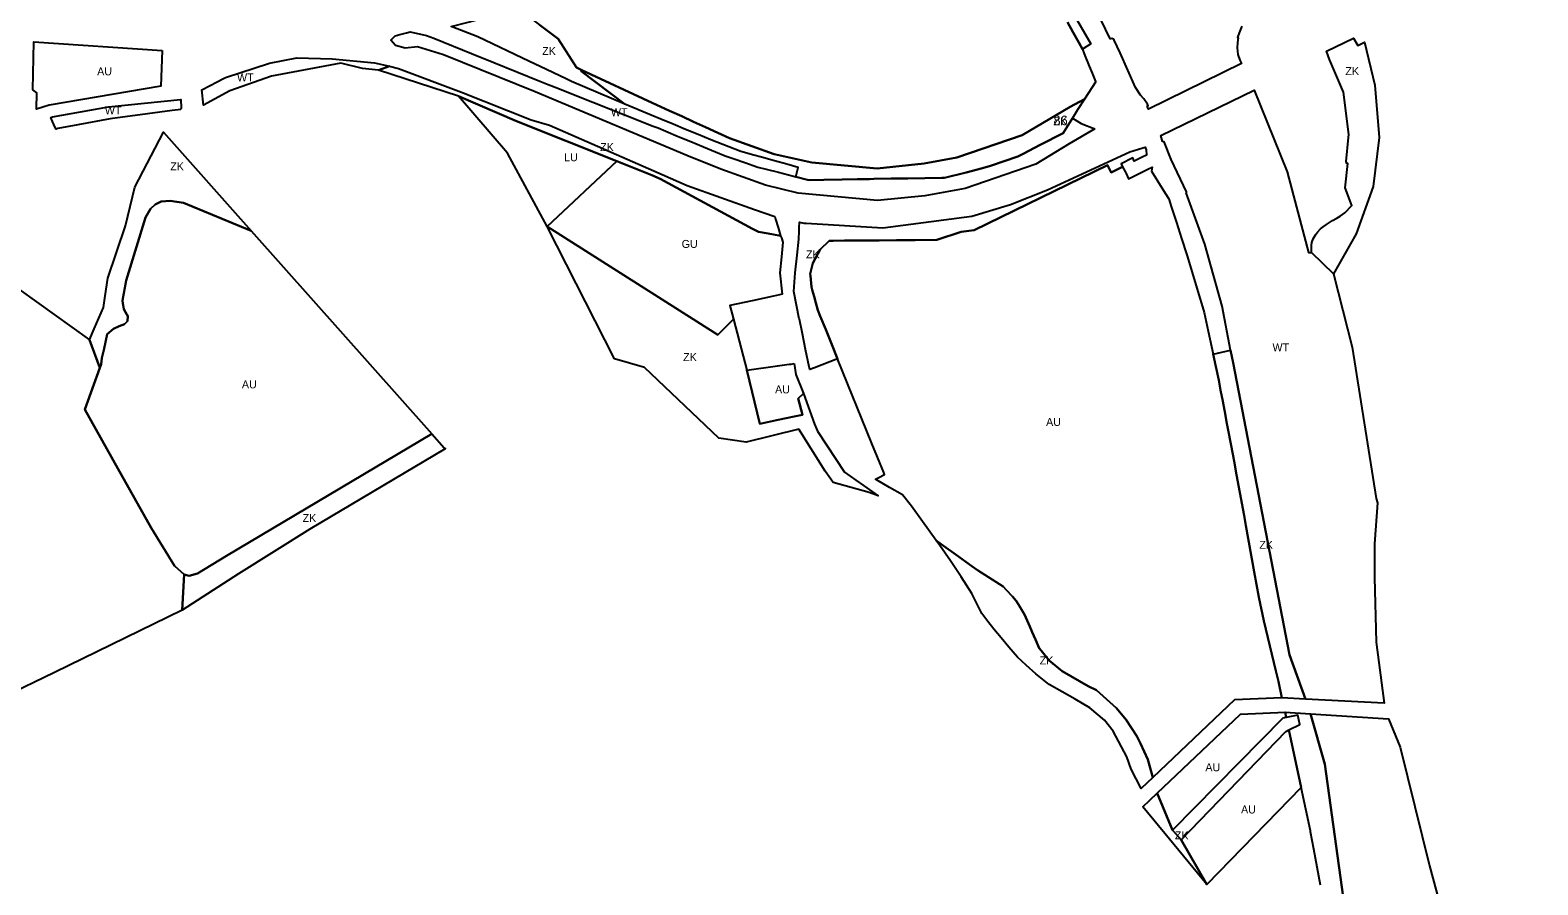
# Model space of a CAD drawing. Extents: x -535894 to -532834, y -1165802 to -1163647.
# Drawn here: x -533821 to -532878, y -1165346 to -1164811 of the extents above; entities that cross this region are included whole.
import ezdxf

# ---------------------------------------------------------------- set-up
doc = ezdxf.new("R2010")
doc.units = 0
for name, color, linetype in [('Vrstva 16', 7, 'Continuous'), ('Vrstva 17', 7, 'Continuous'), ('Vrstva 19', 7, 'Continuous'), ('Vrstva 20', 7, 'Continuous'), ('Vrstva 22', 7, 'Continuous'), ('Vrstva 28', 7, 'Continuous'), ('Vrstva 37', 7, 'Continuous'), ('Vrstva 4', 7, 'Continuous'), ('Vrstva 61', 7, 'Continuous')]:
    doc.layers.add(name, color=color, linetype=linetype)

msp = doc.modelspace()

# ---------------------------------------------------------------- linework, layer by layer
at = {"layer": 'Vrstva 16'}
for points in [[(-533449.329, -1164857.017), (-533482.547, -1164842.741), (-533485.98, -1164841.17), (-533502.187, -1164833.429), (-533508.929, -1164830.209), (-533541.19, -1164814.8), (-533557.97, -1164808.32), (-533538.206, -1164803.326), (-533528.49, -1164803.93), (-533518.46, -1164795.33), (-533502.549, -1164807.296), (-533491.019, -1164815.967), (-533479.52, -1164834.02), (-533476.1, -1164835.72), (-533476.589, -1164836.253)], [(-533019.65, -1164949.83), (-533019.75, -1164945.44), (-533019.74, -1164945.35), (-533019.5, -1164943.61), (-533018.74, -1164941.21), (-533017.27, -1164938.72), (-533016.06, -1164937.15), (-533014.17, -1164935.04), (-533012.47, -1164933.65), (-533010.36, -1164932.29), (-533009.67, -1164931.84), (-533006.56, -1164929.76), (-533003.92, -1164928.32), (-533001.85, -1164927.06), (-532998.95, -1164924.85), (-532994.46, -1164920.43), (-532998.63, -1164909.37), (-532997.02, -1164894.02), (-532997.55, -1164893.98), (-532997.96, -1164892.84), (-532996.596, -1164877.755), (-532996.43, -1164875.92), (-532999.79, -1164849.41), (-533008.53, -1164829.07), (-533010.27, -1164823.69), (-532993.57, -1164815.7), (-532990.84, -1164820.26), (-532986.56, -1164818.1), (-532980.17, -1164845.09), (-532977.31, -1164877.84), (-532981.22, -1164908.52), (-532991.79, -1164937.99), (-533005.91, -1164963.1)], [(-533351.86, -1164939.38), (-533356.31, -1164938.57), (-533359.67, -1164937.97), (-533365.69, -1164936.87), (-533367.68, -1164935.8), (-533369.34, -1164934.9), (-533427.21, -1164903.65), (-533432.31, -1164901.38), (-533454.32, -1164892.58), (-533516.99, -1164867.54), (-533553.28, -1164851.89), (-533603.37, -1164835.56), (-533596.46, -1164833.25), (-533590.786, -1164834.559), (-533551.367, -1164849.4), (-533507.739, -1164866.745), (-533496.424, -1164870.179), (-533431.14, -1164898.61), (-533425.87, -1164900.96), (-533410.244, -1164907.892), (-533368.121, -1164922.828), (-533355.407, -1164927.219), (-533354.932, -1164928.848), (-533353.414, -1164934.051)], [(-533784.18, -1165004.34), (-533781.22, -1164997.48), (-533775.32, -1164984.22), (-533774.28, -1164976.84), (-533772.59, -1164965.85), (-533761.58, -1164933.18), (-533755.71, -1164908.94), (-533737.9, -1164874.36), (-533682.961, -1164936.173), (-533725.33, -1164918.79), (-533733.55, -1164917.49), (-533739.33, -1164917.78), (-533742.93, -1164919.66), (-533745.96, -1164922.55), (-533749, -1164927.89), (-533761.12, -1164967.31), (-533763.43, -1164979.87), (-533763.28, -1164981.75), (-533762.56, -1164985.07), (-533762.13, -1164986.08), (-533760.11, -1164989.55), (-533760.4, -1164992.72), (-533762.27, -1164994.6), (-533765.59, -1164995.9), (-533769.06, -1164997.49), (-533772.95, -1165000.81), (-533774.948, -1165009.851), (-533776.27, -1165015.83), (-533776.85, -1165019.72), (-533777.72, -1165022.03)], [(-533127.88, -1164885.08), (-533123.831, -1164883.862), (-533123.175, -1164885.463), (-533122.912, -1164888.766), (-533125.56, -1164890.06), (-533130.56, -1164892.51), (-533131.5, -1164890.61), (-533138.79, -1164894.19), (-533137.86, -1164896.07), (-533145.13, -1164899.63), (-533147.32, -1164895.13), (-533230.7, -1164935.9), (-533238.8, -1164936.84), (-533254.19, -1164941.95), (-533267.6, -1164942.04), (-533279.34, -1164942.12), (-533290.22, -1164942.19), (-533299.86, -1164942.25), (-533309.61, -1164942.31), (-533311.84, -1164942.33), (-533318.89, -1164942.38), (-533321.4, -1164942.4), (-533327.086, -1164947.81), (-533331.63, -1164956.4), (-533333.27, -1164963.05), (-533333.139, -1164964.439), (-533332.5, -1164971.24), (-533331.983, -1164973.183), (-533330.86, -1164977.41), (-533329.794, -1164981.317), (-533328.55, -1164985.88), (-533327.03, -1164989.6), (-533323.61, -1164998.03), (-533319.84, -1165007.34), (-533316.16, -1165016.4), (-533330.632, -1165021.862), (-533333.62, -1165022.99), (-533333.91, -1165021.36), (-533336.164, -1165010.56), (-533338.183, -1165000.693), (-533340.069, -1164991.475), (-533340.094, -1164991.354), (-533341.865, -1164982.699), (-533343.59, -1164974.269), (-533342.636, -1164962.604), (-533341.509, -1164951.373), (-533340.51, -1164941.413), (-533340.301, -1164936.333), (-533340.209, -1164934.096), (-533340.076, -1164930.725), (-533337.2, -1164931.49), (-533335.892, -1164931.357), (-533287.795, -1164934.442), (-533232.144, -1164926.953), (-533207.984, -1164919.73), (-533184.943, -1164910.649), (-533133.323, -1164886.788)], [(-533340.42, -1165060.46), (-533373.45, -1165068.48), (-533390.5, -1165066.09), (-533436.96, -1165021.83), (-533455.65, -1165016.42), (-533497.72, -1164933.47), (-533391.12, -1165001.26), (-533381.33, -1164991.55), (-533372.98, -1165023.48), (-533364.81, -1165056.97), (-533353.28, -1165054.53), (-533343.29, -1165052.42), (-533338.04, -1165051.31), (-533340.73, -1165041.06), (-533337.57, -1165038.08), (-533330.525, -1165057.282), (-533328.63, -1165061.62), (-533311.86, -1165087.17), (-533304.665, -1165092.211), (-533299.889, -1165095.558), (-533290.68, -1165102.01), (-533296.36, -1165099.92), (-533318.84, -1165093.8), (-533324, -1165086.69)], [(-533038.193, -1165228.594), (-533040.38, -1165218.35), (-533041.97, -1165211.69), (-533049.49, -1165180.28), (-533052.58, -1165165.52), (-533055.7, -1165149.58), (-533060.76, -1165120.61), (-533061.85, -1165114.35), (-533064.51, -1165100.09), (-533066.59, -1165088.96), (-533068.21, -1165080.3), (-533070.04, -1165070.55), (-533072, -1165060.03), (-533072.81, -1165055.68), (-533073.57, -1165051.71), (-533075.28, -1165042.82), (-533076.61, -1165035.87), (-533077.78, -1165029.77), (-533079.658, -1165021.038), (-533081.32, -1165013.31), (-533070.375, -1165010.82), (-533068.828, -1165018.82), (-533033.46, -1165201.68), (-533023.406, -1165229.36)], [(-533724.81, -1165151.41), (-533721.78, -1165152.17), (-533716.48, -1165150.65), (-533698.37, -1165139.6), (-533570, -1165063.27), (-533562.167, -1165071.953), (-533561.35, -1165072.56), (-533561.52, -1165072.67), (-533646.35, -1165122.98), (-533690.81, -1165150.82), (-533726.09, -1165173.68)], [(-533119.066, -1165278.401), (-533126.238, -1165285.22), (-533132.616, -1165273.134), (-533135.154, -1165265.393), (-533143.803, -1165249.375), (-533149.315, -1165242.562), (-533158.312, -1165234.728), (-533167.647, -1165229.437), (-533183.904, -1165220.221), (-533192.12, -1165213.6), (-533198.238, -1165208.072), (-533203.683, -1165203.151), (-533209.065, -1165196.853), (-533213.92, -1165190.884), (-533218.343, -1165185.445), (-533222.253, -1165180.637), (-533225.922, -1165175.806), (-533232.175, -1165163.211), (-533238.958, -1165152.798), (-533245.578, -1165142.723), (-533252.308, -1165133.249), (-533254.581, -1165130.049), (-533251.367, -1165132.338), (-533241.903, -1165139.078), (-533232.151, -1165146.023), (-533228.63, -1165148.53), (-533221.834, -1165152.934), (-533212.69, -1165158.86), (-533210.794, -1165160.894), (-533206.861, -1165165.113), (-533204.43, -1165167.72), (-533202.96, -1165170.109), (-533199.282, -1165176.366), (-533196.01, -1165183.82), (-533194.4, -1165187.49), (-533192.444, -1165191.932), (-533189.98, -1165197.53), (-533188.886, -1165198.883), (-533183.78, -1165205.2), (-533183.758, -1165205.218), (-533175.591, -1165211.807), (-533159.489, -1165221.131), (-533154.28, -1165223.8), (-533141.737, -1165235.035), (-533135.7, -1165242.39), (-533128.91, -1165252.43), (-533126.777, -1165257.07), (-533122.13, -1165267.18)], [(-533116.373, -1165288.26), (-533106.758, -1165311.449), (-533104.858, -1165313.507), (-533101.358, -1165317.299), (-533085.21, -1165345.43), (-533108.53, -1165316.98), (-533125.197, -1165296.649), (-533120.847, -1165292.513)]]:
    msp.add_lwpolyline(points, close=True, dxfattribs=at)
msp.add_lwpolyline([(-533014.2, -1165345.74), (-533018.3, -1165323.32), (-533020.29, -1165312.45), (-533020.4, -1165311.8), (-533026.24, -1165284.54), (-533033.915, -1165248.628), (-533026.975, -1165245.213), (-533028.21, -1165239.43), (-533035.573, -1165240.864), (-533036.286, -1165237.524), (-533020.388, -1165238.55), (-533011.43, -1165270.01), (-532970.84, -1165564.38)], dxfattribs=at)
at = {"layer": 'Vrstva 17'}
msp.add_lwpolyline([(-533449.329, -1164857.017), (-533476.589, -1164836.253), (-533476.1, -1164835.72), (-533432.125, -1164855.996), (-533421.201, -1164861.033), (-533413.65, -1164864.514), (-533406.222, -1164867.94), (-533398.688, -1164871.413), (-533390.995, -1164874.961), (-533383.775, -1164878.254), (-533355.854, -1164888.263), (-533332.237, -1164893.383), (-533291.404, -1164897.211), (-533261.946, -1164894.083), (-533241.514, -1164890.305), (-533200.695, -1164876.243), (-533170.75, -1164858.64), (-533161.703, -1164853.84), (-533166.05, -1164860.58), (-533169.319, -1164865.777), (-533175.17, -1164875.08), (-533189.49, -1164882.49), (-533200, -1164887.93), (-533203.49, -1164889.74), (-533220.52, -1164895.43), (-533225.42, -1164897.07), (-533235.8, -1164899.62), (-533249.36, -1164902.96), (-533251.03, -1164902.99), (-533261.52, -1164903.19), (-533272.33, -1164903.38), (-533282.57, -1164903.56), (-533293.4, -1164903.76), (-533296.3, -1164903.82), (-533303.94, -1164903.95), (-533313.39, -1164904.12), (-533324.7, -1164904.32), (-533333.91, -1164904.48), (-533334.89, -1164904.23), (-533342.327, -1164902.343), (-533341.727, -1164900.001), (-533340.838, -1164896.53), (-533347.953, -1164894.562), (-533355.604, -1164892.445), (-533363.81, -1164890.174), (-533368.48, -1164888.881), (-533376.769, -1164886.588), (-533387.877, -1164882.185), (-533395.416, -1164879.165), (-533403.421, -1164875.924), (-533411.249, -1164872.7), (-533418.937, -1164869.534), (-533426.826, -1164866.284), (-533432.806, -1164863.822)], close=True, dxfattribs=at)
at = {"layer": 'Vrstva 19'}
msp.add_lwpolyline([(-533828.25, -1164972.65), (-533784.18, -1165004.34), (-533777.72, -1165022.03), (-533786.95, -1165048.06), (-533766.306, -1165084.954), (-533745.52, -1165122.1), (-533730.88, -1165145.85), (-533724.81, -1165151.41), (-533726.09, -1165173.68), (-533806.07, -1165212.59), (-533837.937, -1165228.09)], dxfattribs=at)
at = {"layer": 'Vrstva 20'}
msp.add_lwpolyline([(-533183.34, -1164774.65), (-533157.83, -1164819.27), (-533163.04, -1164822.52), (-533165.34, -1164818.38), (-533168.77, -1164812.17), (-533172.45, -1164805.52)], dxfattribs=at)
at = {"layer": 'Vrstva 22'}
msp.add_lwpolyline([(-533172.45, -1164805.52), (-533168.77, -1164812.17), (-533165.34, -1164818.38), (-533163.04, -1164822.52), (-533161.85, -1164825.47), (-533158.74, -1164833.17), (-533156.99, -1164837.52), (-533154.89, -1164842.74), (-533154.75, -1164843.06), (-533161.703, -1164853.84), (-533170.75, -1164858.64), (-533200.695, -1164876.243), (-533241.514, -1164890.305), (-533261.946, -1164894.083), (-533291.404, -1164897.211), (-533332.237, -1164893.383), (-533355.854, -1164888.263), (-533383.775, -1164878.254), (-533390.995, -1164874.961), (-533398.688, -1164871.413), (-533406.222, -1164867.94), (-533413.65, -1164864.514), (-533421.201, -1164861.033), (-533432.125, -1164855.996), (-533476.1, -1164835.72), (-533479.52, -1164834.02), (-533491.019, -1164815.967), (-533502.549, -1164807.296)], dxfattribs=at)
for points in [[(-533738.69, -1164823.39), (-533739.473, -1164845.641), (-533809.264, -1164857.538), (-533817.166, -1164859.962), (-533817.069, -1164849.817), (-533819.587, -1164847.865), (-533818.847, -1164817.831)], [(-533119.066, -1165278.401), (-533122.13, -1165267.18), (-533126.777, -1165257.07), (-533128.91, -1165252.43), (-533135.7, -1165242.39), (-533141.737, -1165235.035), (-533154.28, -1165223.8), (-533159.489, -1165221.131), (-533175.591, -1165211.807), (-533183.758, -1165205.218), (-533183.78, -1165205.2), (-533188.886, -1165198.883), (-533189.98, -1165197.53), (-533192.444, -1165191.932), (-533194.4, -1165187.49), (-533196.01, -1165183.82), (-533199.282, -1165176.366), (-533202.96, -1165170.109), (-533204.43, -1165167.72), (-533206.861, -1165165.113), (-533210.794, -1165160.894), (-533212.69, -1165158.86), (-533221.834, -1165152.934), (-533228.63, -1165148.53), (-533232.151, -1165146.023), (-533241.903, -1165139.078), (-533251.367, -1165132.338), (-533254.581, -1165130.049), (-533258.331, -1165124.77), (-533264.059, -1165116.707), (-533269.885, -1165108.505), (-533275.616, -1165101.51), (-533283.754, -1165096.808), (-533291.871, -1165092.117), (-533292.517, -1165091.744), (-533290.36, -1165090.63), (-533286.76, -1165088.76), (-533287.25, -1165087.56), (-533291.2, -1165077.84), (-533294.68, -1165069.27), (-533316.16, -1165016.4), (-533319.84, -1165007.34), (-533323.61, -1164998.03), (-533327.03, -1164989.6), (-533328.55, -1164985.88), (-533329.794, -1164981.317), (-533330.86, -1164977.41), (-533331.983, -1164973.183), (-533332.5, -1164971.24), (-533333.139, -1164964.439), (-533333.27, -1164963.05), (-533331.63, -1164956.4), (-533327.086, -1164947.81), (-533321.4, -1164942.4), (-533318.89, -1164942.38), (-533311.84, -1164942.33), (-533309.61, -1164942.31), (-533299.86, -1164942.25), (-533290.22, -1164942.19), (-533279.34, -1164942.12), (-533267.6, -1164942.04), (-533254.19, -1164941.95), (-533238.8, -1164936.84), (-533230.7, -1164935.9), (-533147.32, -1164895.13), (-533145.13, -1164899.63), (-533137.86, -1164896.07), (-533136.13, -1164899.58), (-533135.74, -1164900.39), (-533134.16, -1164903.63), (-533132.1, -1164902.62), (-533122.04, -1164897.68), (-533119.37, -1164896.37), (-533119.82, -1164898.82), (-533117.14, -1164903.15), (-533116.11, -1164904.82), (-533111.26, -1164912.65), (-533109.04, -1164916.24), (-533107.52, -1164920.92), (-533104.27, -1164930.9), (-533100.95, -1164941.1), (-533097.74, -1164951.15), (-533094.38, -1164962.37), (-533090.86, -1164974.13), (-533087.36, -1164985.79), (-533086.92, -1164987.26), (-533084.4, -1164998.97), (-533081.32, -1165013.31), (-533079.658, -1165021.038), (-533077.78, -1165029.77), (-533076.61, -1165035.87), (-533075.28, -1165042.82), (-533073.57, -1165051.71), (-533072.81, -1165055.68), (-533072, -1165060.03), (-533070.04, -1165070.55), (-533068.21, -1165080.3), (-533066.59, -1165088.96), (-533064.51, -1165100.09), (-533061.85, -1165114.35), (-533060.76, -1165120.61), (-533055.7, -1165149.58), (-533052.58, -1165165.52), (-533049.49, -1165180.28), (-533041.97, -1165211.69), (-533040.38, -1165218.35), (-533038.193, -1165228.594), (-533067.971, -1165229.821)], [(-533777.72, -1165022.03), (-533776.85, -1165019.72), (-533776.27, -1165015.83), (-533774.948, -1165009.851), (-533772.95, -1165000.81), (-533769.06, -1164997.49), (-533765.59, -1164995.9), (-533762.27, -1164994.6), (-533760.4, -1164992.72), (-533760.11, -1164989.55), (-533762.13, -1164986.08), (-533762.56, -1164985.07), (-533763.28, -1164981.75), (-533763.43, -1164979.87), (-533761.12, -1164967.31), (-533749, -1164927.89), (-533745.96, -1164922.55), (-533742.93, -1164919.66), (-533739.33, -1164917.78), (-533733.55, -1164917.49), (-533725.33, -1164918.79), (-533682.961, -1164936.173), (-533570, -1165063.27), (-533698.37, -1165139.6), (-533716.48, -1165150.65), (-533721.78, -1165152.17), (-533724.81, -1165151.41), (-533730.88, -1165145.85), (-533745.52, -1165122.1), (-533766.306, -1165084.954), (-533786.95, -1165048.06)], [(-533343.416, -1165019.324), (-533342.183, -1165026.234), (-533337.57, -1165038.08), (-533340.73, -1165041.06), (-533338.04, -1165051.31), (-533343.29, -1165052.42), (-533353.28, -1165054.53), (-533364.81, -1165056.97), (-533372.98, -1165023.48), (-533353.73, -1165020.77), (-533346.35, -1165019.74), (-533345.15, -1165019.57)], [(-533037.66, -1165241.27), (-533106.758, -1165311.449), (-533116.373, -1165288.26), (-533064.221, -1165238.674), (-533036.286, -1165237.524), (-533035.573, -1165240.864)], [(-533033.915, -1165248.628), (-533026.24, -1165284.54), (-533085.21, -1165345.43), (-533101.358, -1165317.299), (-533035.85, -1165249.58)]]:
    msp.add_lwpolyline(points, close=True, dxfattribs=at)
at = {"layer": 'Vrstva 28'}
msp.add_lwpolyline([(-533516.99, -1164867.54), (-533454.32, -1164892.58), (-533497.72, -1164933.47), (-533522.7, -1164887.69), (-533553.28, -1164851.89)], close=True, dxfattribs=at)
at = {"layer": 'Vrstva 37'}
msp.add_lwpolyline([(-533367.68, -1164935.8), (-533365.69, -1164936.87), (-533359.67, -1164937.97), (-533356.31, -1164938.57), (-533351.86, -1164939.38), (-533351.34, -1164940.58), (-533350.481, -1164943.362), (-533351.343, -1164952.464), (-533352.303, -1164962.6), (-533350.73, -1164975.81), (-533352.5, -1164976.21), (-533356.25, -1164977.03), (-533369.51, -1164979.95), (-533383.55, -1164983.05), (-533381.33, -1164991.55), (-533391.12, -1165001.26), (-533497.72, -1164933.47), (-533454.32, -1164892.58), (-533432.31, -1164901.38), (-533427.21, -1164903.65), (-533369.34, -1164934.9)], close=True, dxfattribs=at)
at = {"layer": 'Vrstva 4'}
msp.add_lwpolyline([(-533063.41, -1164808.03), (-533064.98, -1164812.34), (-533066.05, -1164815.28), (-533065.52, -1164815.47), (-533066.12, -1164818.42), (-533066.32, -1164821.75), (-533065.88, -1164825.93), (-533064.62, -1164829.31), (-533063.56, -1164831.41), (-533121.79, -1164860.11), (-533122.6, -1164858.35), (-533121.94, -1164858.07), (-533122.39, -1164856.98), (-533124.52, -1164853.64), (-533126.75, -1164851.21), (-533129.85, -1164846.49), (-533139.39, -1164824.708), (-533143.209, -1164816.81), (-533143.6, -1164816.322), (-533144.251, -1164815.953), (-533144.641, -1164815.909), (-533145.227, -1164815.953), (-533145.683, -1164816.04), (-533171.85, -1164761.354)], dxfattribs=at)
for points in [[(-533155.355, -1164872.361), (-533171.4, -1164881.68), (-533192.2, -1164894.47), (-533236.41, -1164909.7), (-533261.61, -1164914.36), (-533291.28, -1164917.31), (-533340.78, -1164912.67), (-533361.33, -1164907.54), (-533389.23, -1164897.67), (-533410.4, -1164889.02), (-533505.42, -1164849.16), (-533562.74, -1164826), (-533578.89, -1164821.11), (-533586.7, -1164821.82), (-533592.59, -1164820.3), (-533595.59, -1164816.83), (-533592.91, -1164814.08), (-533589.91, -1164813.28), (-533585.817, -1164812.22), (-533583.58, -1164811.64), (-533573.32, -1164813.85), (-533568.75, -1164815.7), (-533545.15, -1164825.22), (-533531.09, -1164830.9), (-533502.39, -1164842.48), (-533497.24, -1164844.53), (-533491.23, -1164846.91), (-533487.68, -1164848.33), (-533431.47, -1164870.62), (-533428.43, -1164871.84), (-533423.51, -1164873.88), (-533415.86, -1164877.07), (-533408.04, -1164880.32), (-533400.11, -1164883.63), (-533392.63, -1164886.74), (-533386.52, -1164889.28), (-533381.38, -1164891.04), (-533373.49, -1164893.74), (-533369.05, -1164895.26), (-533365.96, -1164896.32), (-533360.93, -1164897.6), (-533353.15, -1164899.58), (-533343.76, -1164901.98), (-533342.327, -1164902.343), (-533334.89, -1164904.23), (-533333.91, -1164904.48), (-533324.7, -1164904.32), (-533313.39, -1164904.12), (-533303.94, -1164903.95), (-533296.3, -1164903.82), (-533293.4, -1164903.76), (-533282.57, -1164903.56), (-533272.33, -1164903.38), (-533261.52, -1164903.19), (-533251.03, -1164902.99), (-533249.36, -1164902.96), (-533235.8, -1164899.62), (-533225.42, -1164897.07), (-533220.52, -1164895.43), (-533203.49, -1164889.74), (-533200, -1164887.93), (-533189.49, -1164882.49), (-533175.17, -1164875.08), (-533169.319, -1164865.777), (-533163.824, -1164869.081)], [(-533654.486, -1164827.886), (-533632.378, -1164828.501), (-533605.839, -1164831.108), (-533596.46, -1164833.25), (-533603.37, -1164835.56), (-533613.25, -1164834.55), (-533626.96, -1164831.3), (-533670.19, -1164839.35), (-533696.31, -1164848.54), (-533712.834, -1164857.586), (-533713.818, -1164847.949), (-533704.29, -1164842.98), (-533700.79, -1164841.16), (-533699.02, -1164840.23), (-533671.59, -1164831.22)], [(-533023.406, -1165229.36), (-533033.46, -1165201.68), (-533068.828, -1165018.82), (-533070.375, -1165010.82), (-533075.69, -1164983.34), (-533086.39, -1164944.59), (-533098.11, -1164912.42), (-533097.896, -1164912.121), (-533097.918, -1164911.73), (-533107.544, -1164891.527), (-533111.8, -1164880.45), (-533113, -1164880.39), (-533113.94, -1164876.55), (-533055.68, -1164848.17), (-533035.02, -1164899.39), (-533024.33, -1164939.46), (-533021.57, -1164949.83), (-533019.65, -1164949.83), (-533005.91, -1164963.1), (-532994.2, -1165009.04), (-532979.21, -1165103.79), (-532978.36, -1165106.4), (-532980.41, -1165132.1), (-532980.24, -1165153.13), (-532979.22, -1165193.65), (-532974.335, -1165231.899)], [(-533726.94, -1164860.18), (-533728.63, -1164860.41), (-533732.38, -1164860.92), (-533747.79, -1164863), (-533771.09, -1164866.14), (-533791.44, -1164869.9), (-533803.9, -1164872.2), (-533804.975, -1164872.651), (-533805.67, -1164871.11), (-533807.83, -1164866.32), (-533808.265, -1164865.356), (-533807.19, -1164864.79), (-533772.11, -1164858.69), (-533727.16, -1164854.1), (-533726.9, -1164854), (-533726.73, -1164859.25)], [(-532880.194, -1165591.758), (-532908.13, -1165601.07), (-532938.91, -1165611.34), (-532953.65, -1165616.26), (-532955.6, -1165612.74), (-532958.061, -1165604.931), (-532970.84, -1165564.38), (-533011.43, -1165270.01), (-533020.388, -1165238.55), (-532971.48, -1165241.706), (-532964.21, -1165259.48), (-532945.97, -1165333.71), (-532926.98, -1165404.07), (-532896.21, -1165523.88), (-532889.53, -1165558.14), (-532878.16, -1165591.08)]]:
    msp.add_lwpolyline(points, close=True, dxfattribs=at)

# ---------------------------------------------------------------- texts
at = {"layer": 'Vrstva 16'}
for rotation, p in [(360, (-533500.9479, -1164826.1735)), (359.9999999, (-532998.53, -1164838.7122)), (360, (-533464.6861, -1164886.315)), (0.0000001, (-533733.5705, -1164898.3611)), (360, (-533335.8859, -1164953.426)), (360, (-533412.7854, -1165017.74)), (0.0000001, (-533650.7982, -1165118.475)), (0, (-533052.363, -1165135.252)), (359.9999999, (-533189.7424, -1165207.6345)), (0.0000001, (-533105.2035, -1165317.0855))]:
    msp.add_text('ZK', height=5, rotation=rotation, dxfattribs=at).set_placement(p)
at = {"layer": 'Vrstva 17'}
msp.add_text('ZK', height=5, rotation=360, dxfattribs=at).set_placement((-533181.1414, -1164870.1))
at = {"layer": 'Vrstva 22'}
for rotation, p in [(0, (-533779.3008, -1164838.8965)), (0, (-533688.7678, -1165034.83)), (360, (-533355.275, -1165037.9698)), (360, (-533185.7315, -1165058.3488)), (0, (-533086.1258, -1165274.4865)), (360, (-533063.799, -1165300.8971))]:
    msp.add_text('AU', height=5, rotation=rotation, dxfattribs=at).set_placement(p)
at = {"layer": 'Vrstva 28'}
msp.add_text('LU', height=5, rotation=0.0000001, dxfattribs=at).set_placement((-533487.2017, -1164892.68))
at = {"layer": 'Vrstva 37'}
msp.add_text('GU', height=5, rotation=360, dxfattribs=at).set_placement((-533413.6939, -1164946.92))
at = {"layer": 'Vrstva 4'}
for rotation, p in [(0, (-533691.8173, -1164842.736)), (0, (-533774.4866, -1164863.3255)), (0, (-533457.9388, -1164864.475)), (360, (-533044.1375, -1165011.6305))]:
    msp.add_text('WT', height=5, rotation=rotation, dxfattribs=at).set_placement(p)
at = {"layer": 'Vrstva 61'}
msp.add_text('86', height=6, rotation=360, dxfattribs=at).set_placement((-533181.1414, -1164870.1))

doc.saveas('drawing.dxf')
